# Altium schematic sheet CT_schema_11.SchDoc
size 741 x 377 mm
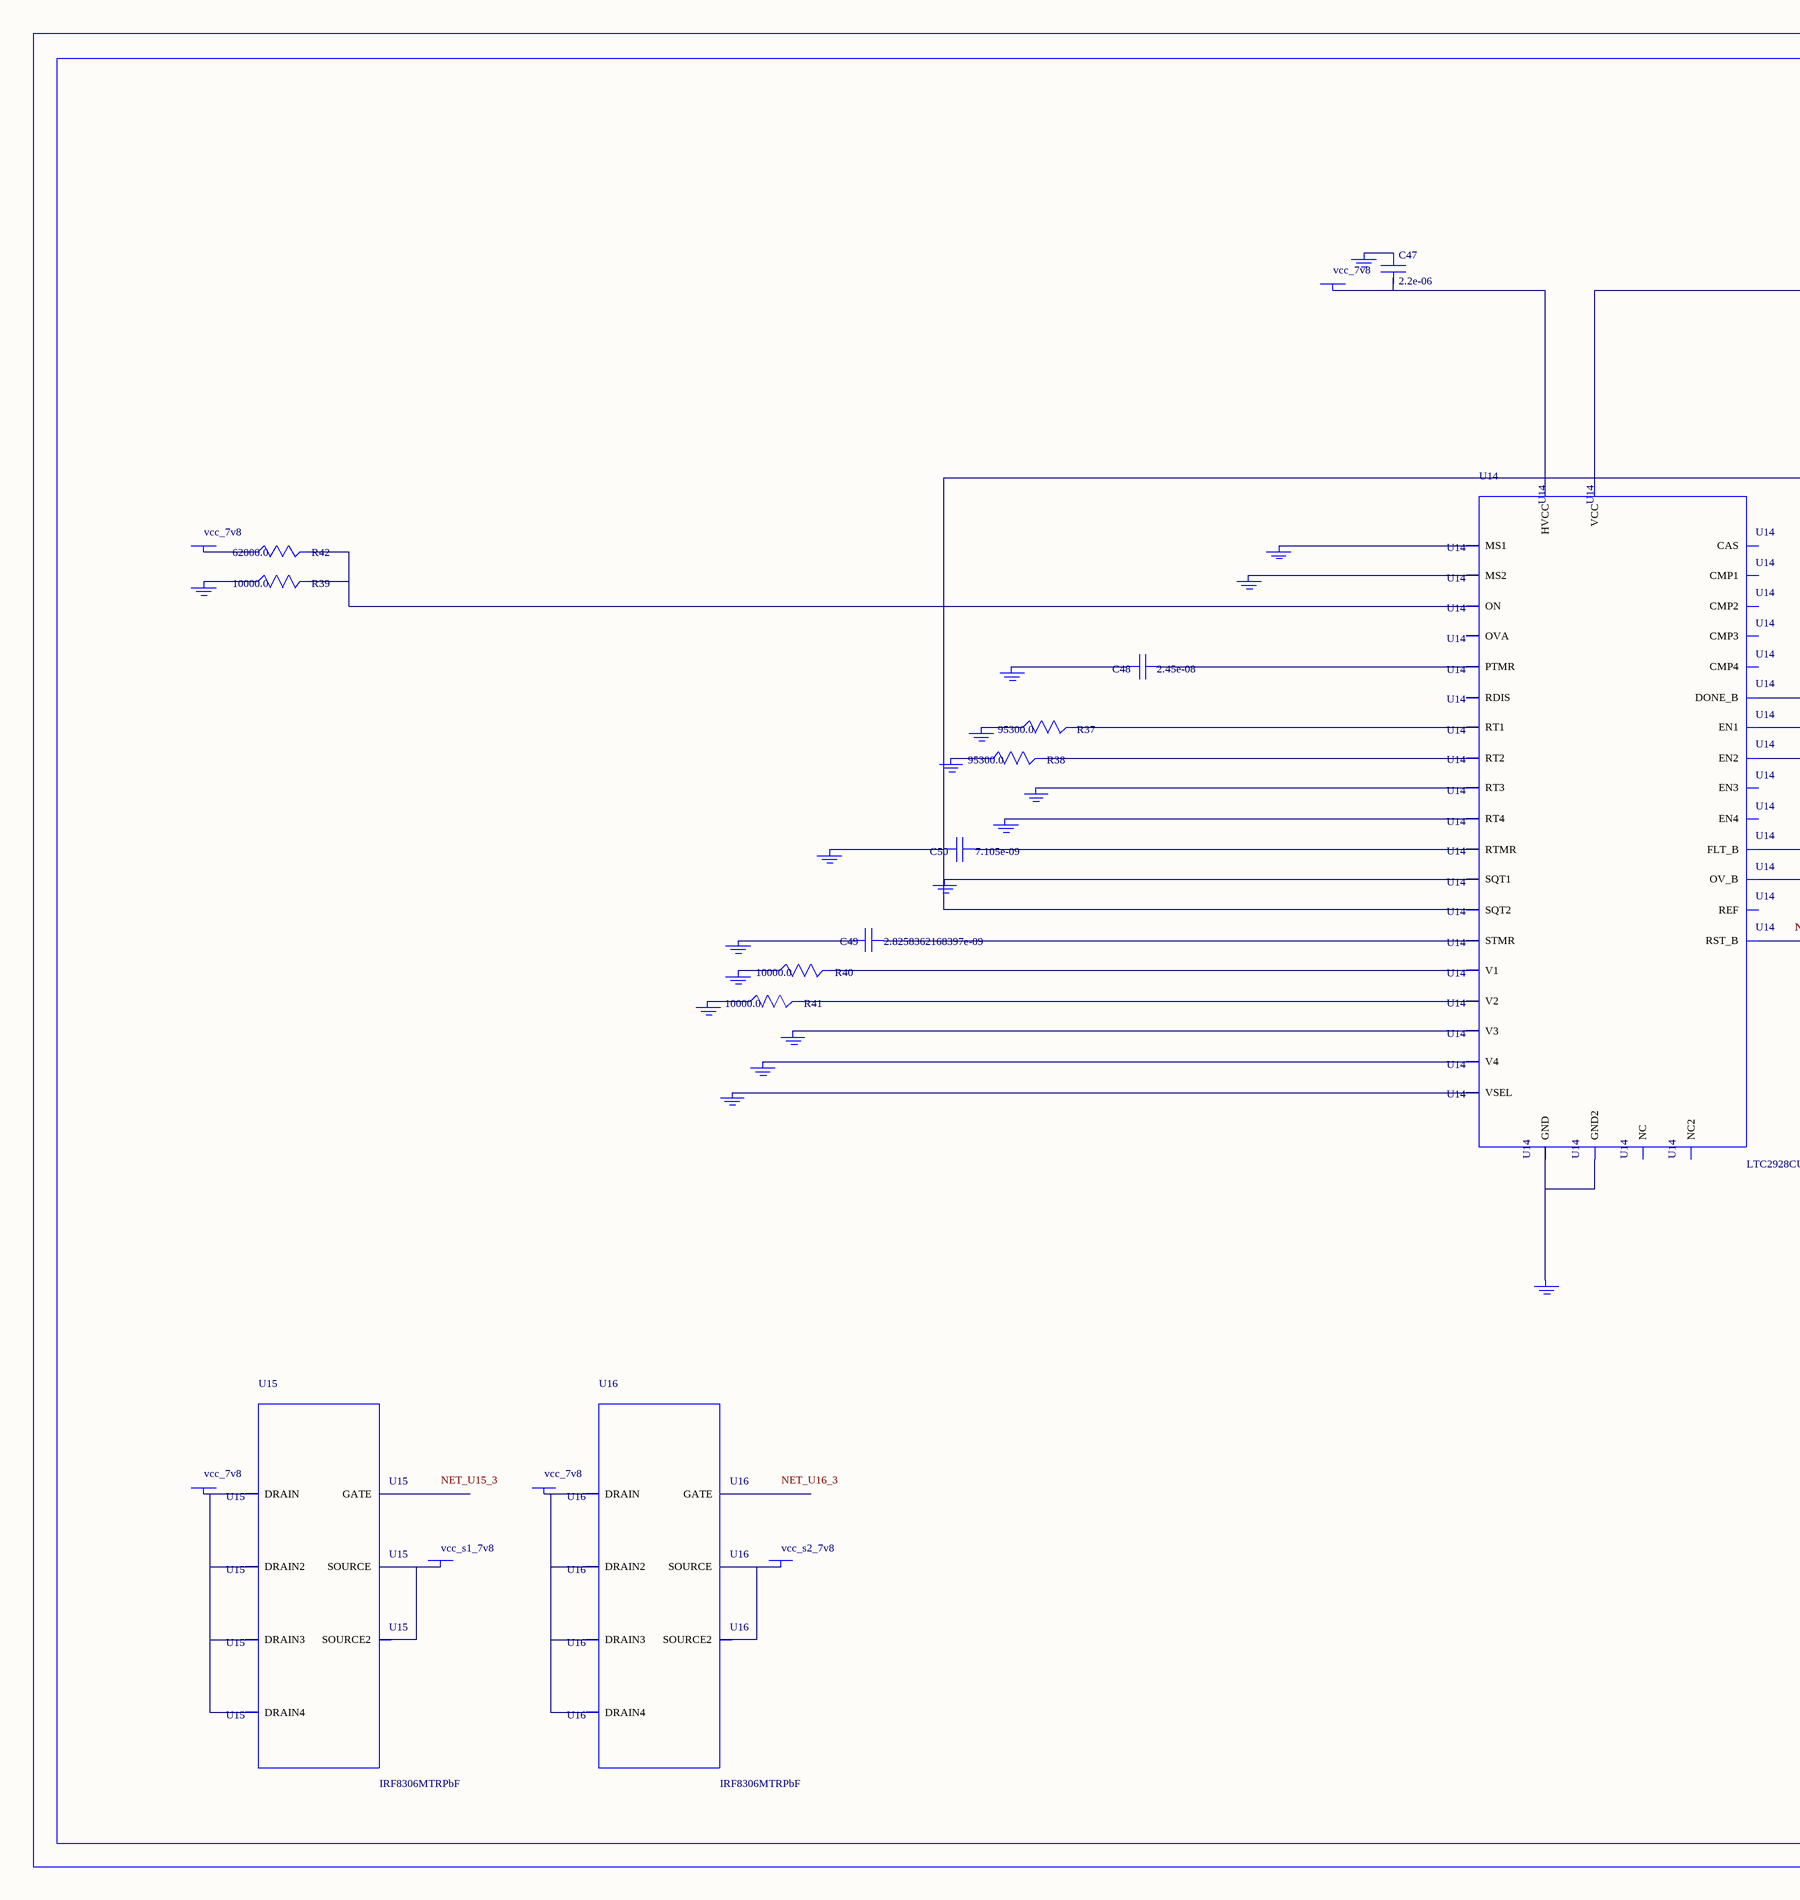
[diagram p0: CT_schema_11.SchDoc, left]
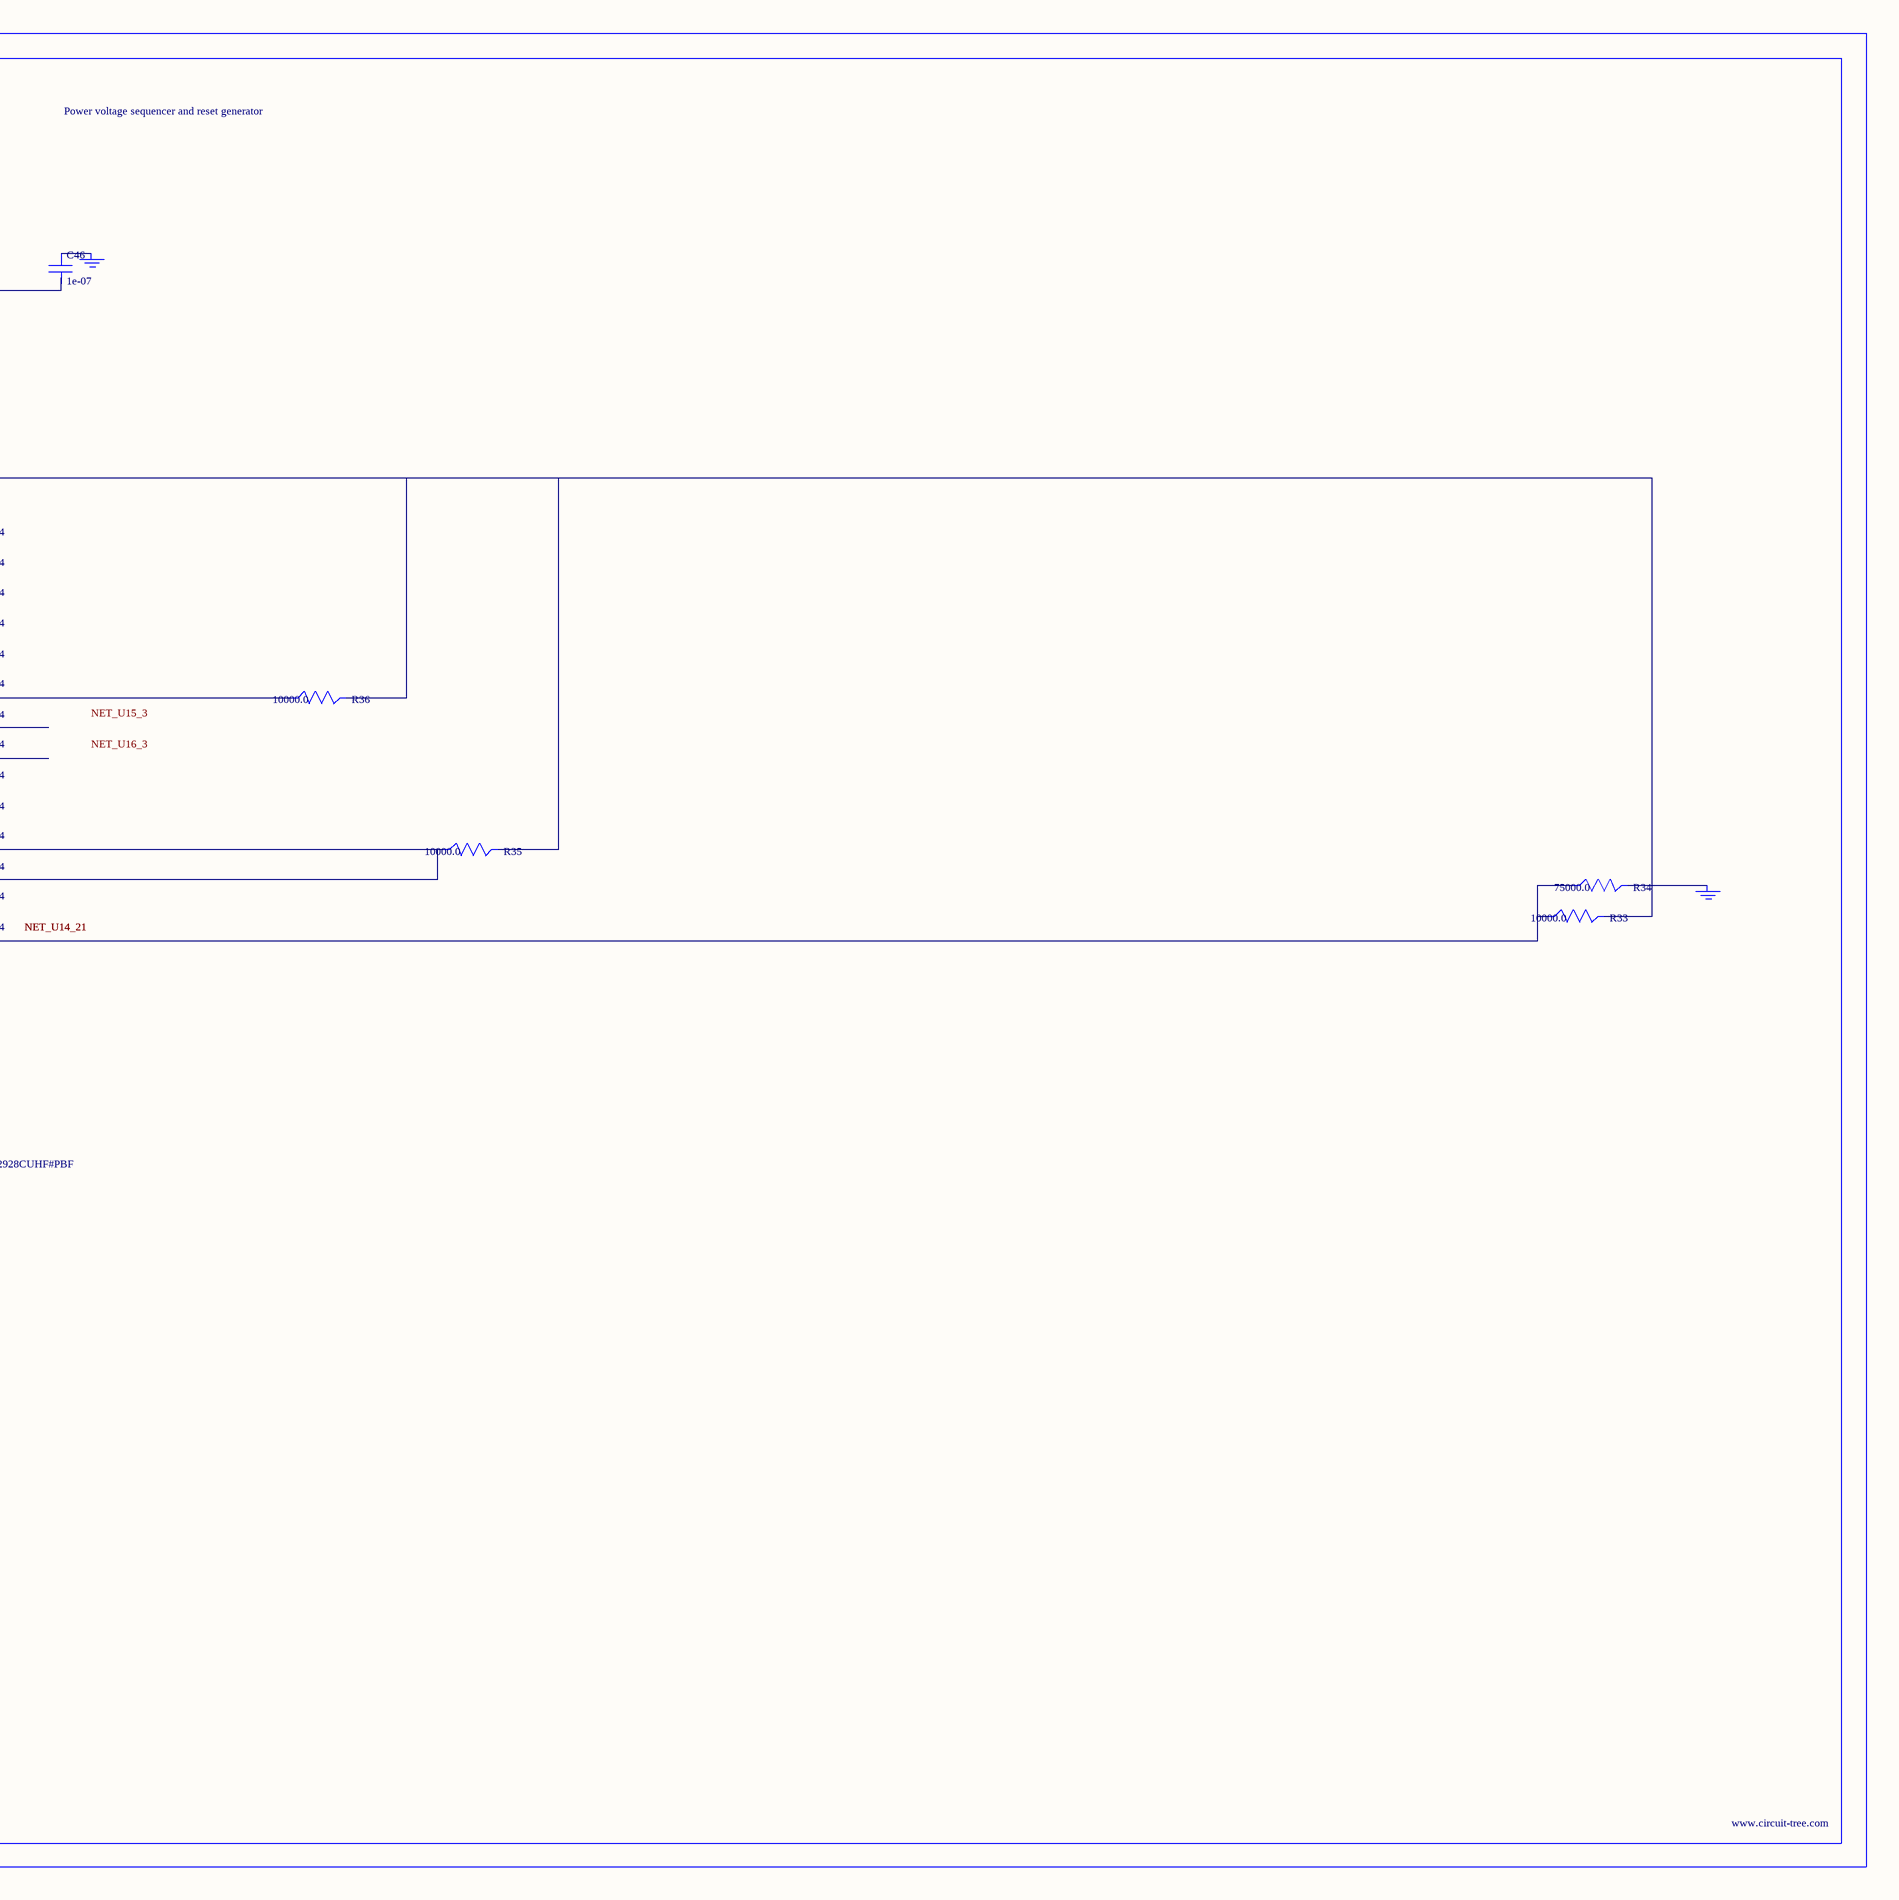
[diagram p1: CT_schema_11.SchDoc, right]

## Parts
BORDER10  (no value)
C46  1e-07  [C0402]
C47  2.2e-06  [C0603]
C48  2.45e-08  [R0603]
C49  2.8258362168397e-09  [R0603]
C50  7.105e-09  [R0603]
GND_INSTANCE_10_0  (no value)
GND_INSTANCE_10_1  (no value)
GND_INSTANCE_10_2  (no value)
GND_INSTANCE_10_3  (no value)
GND_INSTANCE_10_4  (no value)
GND_INSTANCE_10_5  (no value)
GND_INSTANCE_10_6  (no value)
GND_INSTANCE_10_7  (no value)
GND_INSTANCE_10_8  (no value)
GND_INSTANCE_10_9  (no value)
GND_INSTANCE_10_10  (no value)
GND_INSTANCE_10_11  (no value)
GND_INSTANCE_10_12  (no value)
GND_INSTANCE_10_13  (no value)
GND_INSTANCE_10_14  (no value)
GND_INSTANCE_10_15  (no value)
GND_INSTANCE_10_16  (no value)
GND_INSTANCE_10_17  (no value)
GND_INSTANCE_10_18  (no value)
GND_INSTANCE_10_19  (no value)
POWER_INSTANCE_10_0  vcc_7v8
POWER_INSTANCE_10_1  vcc_7v8
POWER_INSTANCE_10_2  vcc_7v8
POWER_INSTANCE_10_3  vcc_s1_7v8
POWER_INSTANCE_10_4  vcc_7v8
POWER_INSTANCE_10_5  vcc_s2_7v8
R33  10000.0  [R0603]
R34  75000.0  [R0603]
R35  10000.0  [R0603]
R36  10000.0  [R0603]
R37  95300.0  [R0603]
R38  95300.0  [R0603]
R39  10000.0  [R0603]
R40  10000.0  [R0603]
R41  10000.0  [R0603]
R42  62000.0  [R0603]
U14  LTC2928CUHF#PBF  [QFN-38_UHF]
U15  IRF8306MTRPbF  [IRF8306MTRPBF]
U16  IRF8306MTRPbF  [IRF8306MTRPBF]

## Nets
NetC46_1: C46.1 GND_INSTANCE_10_10.0(GND)
NetC46_2: C46.2 C50.2 GND_INSTANCE_10_5.0(GND) GND_INSTANCE_10_15.0(GND) R33.2 R35.2 R36.2 U14.10(SQT1) U14.11(SQT2) U14.22(VCC)
NetC47_1: C47.1 GND_INSTANCE_10_11.0(GND)
NetC47_2: C47.2 POWER_INSTANCE_10_1.0(PWR) U14.23(HVCC)
NetC48_1: C48.1 U14.27(PTMR)
NetC48_2: C48.2 GND_INSTANCE_10_14.0(GND)
NetC49_1: C49.1 U14.26(STMR)
NetC49_2: C49.2 GND_INSTANCE_10_13.0(GND)
NetC50_1: C50.1 U14.28(RTMR)
NetGND_INSTANCE_10_0_0: GND_INSTANCE_10_0.0(GND) R40.1
NetGND_INSTANCE_10_1_0: GND_INSTANCE_10_1.0(GND) R37.1
NetGND_INSTANCE_10_2_0: GND_INSTANCE_10_2.0(GND) R38.1
NetGND_INSTANCE_10_3_0: GND_INSTANCE_10_3.0(GND) U14.8(RT3)
NetGND_INSTANCE_10_4_0: GND_INSTANCE_10_4.0(GND) U14.9(RT4)
NetGND_INSTANCE_10_6_0: GND_INSTANCE_10_6.0(GND) U14.12(MS1)
NetGND_INSTANCE_10_7_0: GND_INSTANCE_10_7.0(GND) U14.13(MS2)
NetGND_INSTANCE_10_8_0: GND_INSTANCE_10_8.0(GND) R39.1
NetGND_INSTANCE_10_9_0: GND_INSTANCE_10_9.0(GND) R34.2
NetGND_INSTANCE_10_12_0: GND_INSTANCE_10_12.0(GND) U14.25(VSEL)
NetGND_INSTANCE_10_16_0: GND_INSTANCE_10_16.0(GND) U14.30(V4)
NetGND_INSTANCE_10_17_0: GND_INSTANCE_10_17.0(GND) U14.32(V3)
NetGND_INSTANCE_10_18_0: GND_INSTANCE_10_18.0(GND) R41.1
NetGND_INSTANCE_10_19_0: GND_INSTANCE_10_19.0(GND) U14.24(GND) U14.39(GND2)
NetPOWER_INSTANCE_10_0_0: POWER_INSTANCE_10_0.0(PWR) R42.1
NetPOWER_INSTANCE_10_2_0: POWER_INSTANCE_10_2.0(PWR) U15.1(DRAIN) U15.2(DRAIN2) U15.6(DRAIN3) U15.7(DRAIN4)
NetPOWER_INSTANCE_10_3_0: POWER_INSTANCE_10_3.0(PWR) U15.4(SOURCE) U15.5(SOURCE2)
NetPOWER_INSTANCE_10_4_0: POWER_INSTANCE_10_4.0(PWR) U16.1(DRAIN) U16.2(DRAIN2) U16.6(DRAIN3) U16.7(DRAIN4)
NetPOWER_INSTANCE_10_5_0: POWER_INSTANCE_10_5.0(PWR) U16.4(SOURCE) U16.5(SOURCE2)
NetR33_1: R33.1 R34.1 U14.21(RST_B)
NetR35_1: R35.1 U14.19(FLT_B) U14.20(OV_B)
NetR36_1: R36.1 U14.18(DONE_B)
NetR37_2: R37.2 U14.6(RT1)
NetR38_2: R38.2 U14.7(RT2)
NetR39_2: R39.2 R42.2 U14.16(ON)
NetR40_2: R40.2 U14.3(V1)
NetR41_2: R41.2 U14.38(V2)

Not connected (* = marked no-connect by the designer): U14 1(OVA) 2(EN1) 4(NC) 5(REF) 14(RDIS) 15(CAS) 17(NC2) 29(EN4) 31(EN3) 33(CMP3) 34(CMP4) 35(CMP1) 36(CMP2) 37(EN2); U15 3(GATE); U16 3(GATE)

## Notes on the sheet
- Labels drawn without touching a wire or pin: NET_U15_3, NET_U16_3

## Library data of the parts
BORDER10 = BORDER_PAGE10
C46 = C0402C104K3RACTU
C47 = GRM188R61H225KE1115D
C48 = C48
C49 = C49
C50 = C50
GND_INSTANCE_10_0-GND_INSTANCE_10_19 = GND
POWER_INSTANCE_10_0-POWER_INSTANCE_10_5 = PWR
R33 R35 R36 R39-R41 = RC0603JR-0710KL
R34 = RC0603JR-0775KL
R37 R38 = RC0603FR-0795K3L
R42 = RC0603JR-0762KL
